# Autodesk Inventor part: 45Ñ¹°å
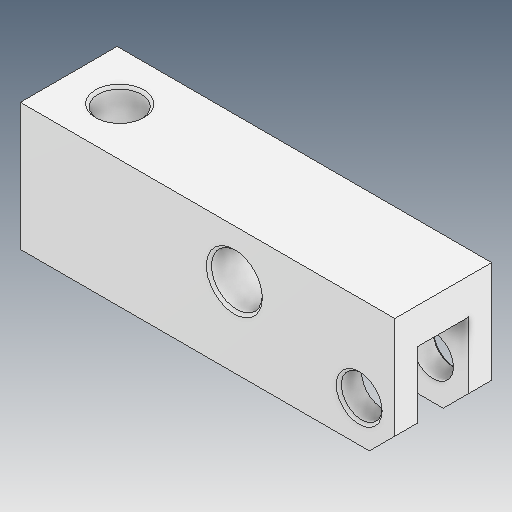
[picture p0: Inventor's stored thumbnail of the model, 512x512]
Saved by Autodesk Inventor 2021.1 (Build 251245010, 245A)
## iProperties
Created: 2021-05
Part Number: 45Ñ¹°å
Material: Ogólny
Document SubType Name: Modeling
Designer: user
Density: 1 g/cm^3
Appearance: Domyślna
Author: user
Revision Number: ÈÎºÎ
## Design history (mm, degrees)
feature "ÊäÈë1"
node "Bryła1"
